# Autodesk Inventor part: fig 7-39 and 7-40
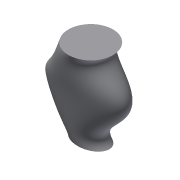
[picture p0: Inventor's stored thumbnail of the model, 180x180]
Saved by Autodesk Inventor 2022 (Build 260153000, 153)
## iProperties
Part Number: fig 7-39 and 7-40
Document SubType Name: Modeling
Created: 2002-12
Designer: deepak
Density: 1 g/cm^3
Material: Generic
Appearance: Default
Control State: 0
Master: False
Checked Out: False
Shininess: 64.0
Length Units: 11269
Angle Units: 11279
Time Units: 11290
Mass Units: 11283
Length Display Precision: 3
Angle Display Precision: 2
Compacted: True
Density: 0.0
Volumn: 0.0
Area: 0.0
PropertySet Name: Model Information
Author: deepak
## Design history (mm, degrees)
sketch "Sketch1"
  geometry: 2 further points; 1 other entity
  constraints: 1 coincident, 3 other
workplane "Work Plane1"
workplane "Work Plane2"
sketch "Sketch3"
  geometry: C1 r 60 at (0, 0); 1 further point
  constraints: 1 centre point, 1 coincident, 1 other
sketch "Sketch4"
  geometry: 8 further points
  constraints: 8 other
sketch "Sketch5"
  geometry: 6 further points
  constraints: 6 other
sketch "Sketch6"
  geometry: 6 further points
  constraints: 6 other
  dimensions: "d20" = 35 distance of point (0, 0) point (-35, 0); "d21" = 0 vertical distance of point (0, 0) point (-35, 0); "d22" = 225 vertical distance of point (0, 0) point (-60, 225); "d23" = 60 horizontal distance of point (0, 0) point (-60, 225); "d24" = 100 horizontal distance of point (0, 0) point (-100, 125); "d25" = 125 vertical distance of point (0, 0) point (-100, 125)
loft "Loft3" dims "d42" = 0, "d43" = 90 deg, "d44" = 0, "d45" = 90 deg, "d46" = 0, "d47" = 90 deg, "d48" = 0, "d49" = 90 deg
node "Sketch7"
sketch "Sketch8"
  geometry: 1 further point
body "Solid1"
other parameters: "d5" = 125
